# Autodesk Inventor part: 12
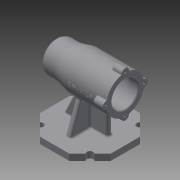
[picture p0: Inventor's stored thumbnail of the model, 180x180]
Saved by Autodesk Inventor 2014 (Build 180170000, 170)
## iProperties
Created: 2019-12
Part Number: 12
Material: 일반
Document SubType Name: Modeling
Designer: NET
Density: 1 g/cm^3
Appearance: 기본값
Author: NET
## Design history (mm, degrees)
sketch "스케치1"
  geometry: L1 (0, 56)-(0, -56); L2 (0, 56)-(-30, 56); L3 (-30, 56)-(-30, -11); L4 (-30, -11)-(-25, -31); L5 (-25, -31)-(-25, -56); L6 (-25, -56)-(0, -56); L7 (-21, 56)-(-21, 41); L8 (-21, 41)-(-21, 41); L9 (-24, 38)-(-24, -10); L10 (-21, -13)-(-21, -13); L11 (-21, -13)-(-21, -24.7); L12 (-20.7, -25)-(-17.5, -25); L13 (-17.5, -25)-(-17.5, -42.7); L14 (-17.2, -43)-(-16, -43); L15 (-16, -43)-(-16, -46.7); L16 (-15.7, -47)-(-10.5, -47); L17 (-10.5, -47)-(-10.5, -47); L18 (-7.5, -50)-(0, -50); A1 r 3 centre (-7.5, -47) between (-10.5, -47) and (-7.5, -50); A2 r 3 centre (-21, -10) between (-24, -10) and (-21, -13); A3 r 3 centre (-21, 38) between (-21, 41) and (-24, 38); A4 r 0.3 centre (-20.7, -24.7) between (-21, -24.7) and (-20.7, -25); A5 r 0.3 centre (-17.2, -42.7) between (-17.5, -42.7) and (-17.2, -43); A6 r 0.3 centre (-15.7, -46.7) between (-16, -46.7) and (-15.7, -47); 8 further points
  constraints: 36 end point, 14 point on line, 12 point on circle, 12 tangent, 9 perpendicular, 7 parallel, 6 centre point, 3 equal radius, 1 coincident, 1 midpoint, 1 vertical
  dimensions: "d0" = 112 distance of L1.start L1.end; "d1" = 60 diameter of L3 L1; "d2" = 45 vertical distance of L5.end L3.end; "d3" = 25 distance of L4.end L5.end; "d4" = 50 diameter of L5 L1; "d5" = 15 distance of L7.start L7.end; "d6" = 54 distance of point (-24, 41) point (-24, -13); "d7" = 12 distance of L10.end point (-21, -25); "d8" = 18 distance of L12.end point (-17.5, -43); "d9" = 4 distance of L14.end point (-16, -47); "d10" = 3 distance of L16.end point (-10.5, -50); "d11" = 42 diameter of L7 L1; "d12" = 48 diameter of L9 L1; "d13" = 42 diameter of L11 L1; "d14" = 35 diameter of L13 L1; "d15" = 32 diameter of L15 L1; "d16" = 21 diameter of L17 L1; "d17" = 3 radius of A1; "d18" = 0.3 radius of A4; "d19" = 0.3 radius of A5
revolve "회전1" sketch "스케치1" stored, may be unused: angle "d20" = 90 deg
fillet "모깎기1" dims "d21" = 10
chamfer "모따기1" distance "d22" = 1; stored, may be unused: second distance "d23" = 2, angle "d24" = 45 deg
fillet "모깎기2" dims "d25" = 3
sketch "스케치2" dims "d26" = 60
  geometry: L1 (0, 0)-(0, 30); C1 r 22 at (0, 0) reference; A1 r 30 centre (0, 0) between (5.97, 29.4) and (-5.97, 29.4) reference; A2 r 6 centre (0, 30) between (5.97, 29.4) and (-5.97, 29.4)
  constraints: 4 point on circle, 2 coincident, 2 end point, 1 centre point, 1 vertical, 1 vertical alignment, 2 other
  dimensions: "d27" = 6 radius of A2
extrude "돌출1" join sketch "스케치2" distance "d28" = 16; taper "d29" = 0 deg
hole "구멍1" diameter "d32" = 3.242; stored, may be unused: countersink angle "d36" = 90 deg, drill point angle "d38" = 118 deg; dims "d30" = 10, "d31" = 10, "d33" = 8, "d34" = 4, "d35" = 2, "d37" = 11
fillet "모깎기3" dims "d42" = 3
fillet "모깎기4" dims "d43" = 1
node "작업 평면1"
sketch "스케치3"
  geometry: L1 (23.196, -56)-(-23.196, -56); L2 (-56, -23.196)-(-56, 23.196); L3 (-23.196, 56)-(23.196, 56); L4 (56, 23.196)-(56, -23.196); L5 (-43.134, -36.062)-(-56, -23.196); L6 (-36.062, -43.134)-(-23.196, -56); L7 (36.062, -43.134)-(23.196, -56); L8 (43.134, -36.062)-(56, -23.196); L9 (43.134, 36.062)-(56, 23.196); L10 (36.062, 43.134)-(23.196, 56); L11 (-36.062, 43.134)-(-23.196, 56); L12 (-43.134, 36.062)-(-56, 23.196); A1 r 5 centre (-39.598, 39.598) between (-43.134, 36.062) and (-36.062, 43.134); A2 r 5 centre (39.598, 39.598) between (36.062, 43.134) and (43.134, 36.062); A3 r 5 centre (39.598, -39.598) between (43.134, -36.062) and (36.062, -43.134); A4 r 5 centre (-39.598, -39.598) between (-36.062, -43.134) and (-43.134, -36.062); 1 further point
  constraints: 24 end point, 8 point on circle, 6 equal length, 4 centre point, 2 perpendicular, 1 horizontal
  dimensions: "d51" = 10 diameter of A1; "d52" = 10 diameter of A2; "d53" = 10 diameter of A3; "d54" = 10 diameter of A4
extrude "돌출2" join sketch "스케치3" distance "d55" = 10; taper "d56" = 0 deg
sketch "스케치4"
  geometry: L1 (-70, 56)-(-70, 43.134) reference; L2 (-70, 36.062)-(-70, 23.196) reference; L3 (-70, 43.134)-(-70, 34.598) reference; L4 (-70, 23.196)-(-70, -23.196) reference; L5 (-70, -23.196)-(-70, -36.062) reference; L6 (-70, -34.598)-(-70, -43.134) reference; L7 (-70, -43.134)-(-70, -56) reference; L8 (-24.361, 31)-(-75.012, 31); L9 (-70, -38)-(-26.366, -17.653); L10 (-26.366, 31)-(-26.366, -18.494); L11 (-70, 31)-(-70, -38); 1 further point
  constraints: 8 end point, 5 point on line, 2 perpendicular
  dimensions: "d58" = 18 distance of L9.start L7.end; "d60" = 115 deg angle of L7 L9; "d61" = 25 distance from line of L1.start L8
extrude "돌출3" join sketch "스케치4" stored distance "d62" = 8; taper "d63" = 0 deg
sketch "스케치5"
  geometry: L1 (-23.196, -70)-(23.196, -70) reference; L2 (-36.062, -70)-(-23.196, -70) reference; L3 (-43.134, -70)-(-34.598, -70) reference; L4 (-56, -70)-(-43.134, -70) reference; L5 (23.196, -70)-(36.062, -70) reference; L6 (34.598, -70)-(43.134, -70) reference; L7 (43.134, -70)-(56, -70) reference; L8 (-36, -70)-(-17.997, -20.536); L9 (36, -70)-(18.979, -23.234); L10 (-36, -70)-(36, -70); A1 r 30 centre (0, 0) between (-18.979, -23.234) and (18.979, -23.234); 1 further point
  constraints: 6 end point, 3 point on line, 2 point on circle, 1 centre point, 1 coincident, 1 collinear
  dimensions: "d64" = 60 diameter of A1; "d65" = 20 distance of L4.start L8.start; "d66" = 20 distance of L7.end L9.start; "d68" = 110 deg angle of L6 L9; "d69" = 110 deg angle of L4 L8
extrude "돌출4" join sketch "스케치5" stored distance "d70" = 8; taper "d71" = 0 deg
fillet "모깎기5" dims "d72" = 3
fillet "모깎기6" dims "d73" = 3
fillet "모깎기7" dims "d74" = 3
node "작업 평면2"
sketch "스케치6"
  geometry: L1 (-6.771, 33.5)-(-29.226, 33.5) reference; 2 further points
  constraints: 1 other
  dimensions: "d75" = 41 distance from line of L1 point (0, -7.5); "d76" = 0 horizontal distance of point (0, -22.5) point (0, -7.5)
feature "엠보싱1" sketch "스케치6" dims "d0" = 112, "d1" = 60, "d2" = 45, "d3" = 25, "d4" = 50, "d5" = 15, "d6" = 54, "d7" = 12, "d8" = 18, "d9" = 4, "d10" = 3, "d11" = 42, "d12" = 48, "d13" = 42, "d14" = 35, "d15" = 32, "d16" = 21, "d17" = 3, "d18" = 0.3, "d19" = 0.3, "d77" = 0.5, "d78" = 0
node "솔리드1"
pattern_circular "원형 패턴1" dims angle "d40" = 360 deg
